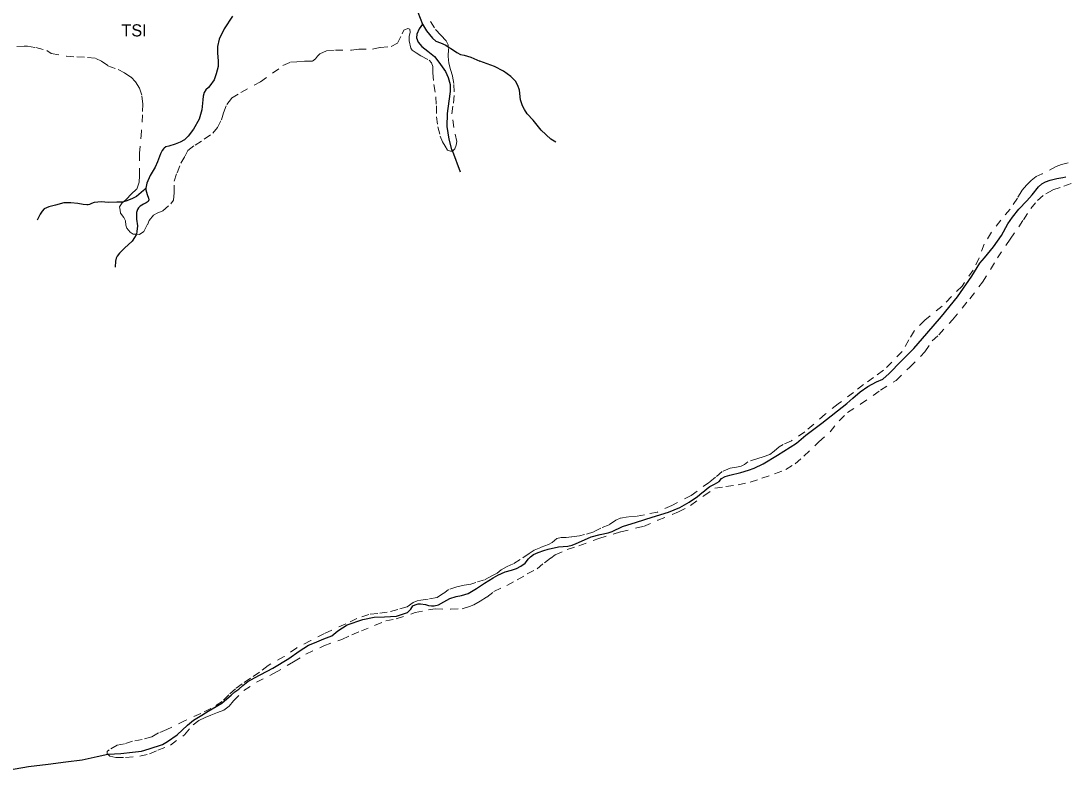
# Model space of a CAD drawing. Extents: x 391.8 to 446, y 8452 to 8507.5.
# Drawn here: x 417.52 to 431.31, y 8489.64 to 8499.54 of the extents above; entities that cross this region are included whole.
import ezdxf
from ezdxf.enums import TextEntityAlignment as Align

# ---------------------------------------------------------------- set-up
doc = ezdxf.new("R2010")
doc.units = 0
doc.header["$LTSCALE"] = 0.064
doc.linetypes.add('LONG_DASHED', pattern=[7.5, 6, -1.5])
doc.linetypes.add('SHORT_DASHED', pattern=[2.7, 1.5, -1.2])
for name, color, linetype, lineweight in [('21', 7, 'SHORT_DASHED', 13), ('7', 7, 'Continuous', 25), ('9', 7, 'LONG_DASHED', 25)]:
    doc.layers.add(name, color=color, linetype=linetype, lineweight=lineweight)
doc.layers.add('61', color=7, linetype='Continuous')

msp = doc.modelspace()

# ---------------------------------------------------------------- linework, layer by layer
at = {"layer": '21'}
for points in [[(423.171, 8499.1938), (423.167, 8499.2216), (423.1413, 8499.273), (423.0706, 8499.35), (422.9866, 8499.444), (422.9094, 8499.5788)], [(422.2702, 8499.1845), (422.418, 8499.1974), (422.5016, 8499.2423), (422.5594, 8499.3643), (422.5851, 8499.4156), (422.6366, 8499.4349), (422.6623, 8499.4285), (422.6687, 8499.39), (422.6559, 8499.3322), (422.6559, 8499.2744), (422.6751, 8499.1781), (422.6944, 8499.1524), (422.7459, 8499.1139), (422.8101, 8499.0754), (422.9194, 8499.0176), (422.9485, 8498.9841), (422.9678, 8498.9328), (422.9678, 8498.8493), (422.9806, 8498.6952), (423.0064, 8498.5347), (423.0128, 8498.4128), (423.0128, 8498.2715), (423.0321, 8498.1367), (423.0642, 8498.0147), (423.0964, 8497.9377), (423.1285, 8497.8799), (423.1606, 8497.8286), (423.1992, 8497.8157), (423.2247, 8497.8157)], [(417.468, 8499.1981), (417.5644, 8499.2045), (417.6094, 8499.2045), (417.7187, 8499.1852), (417.8665, 8499.1467), (417.9244, 8499.1082), (418.1237, 8499.0697), (418.2612, 8499.061), (418.4026, 8499.0546), (418.5119, 8499.0418), (418.5891, 8499.0033), (418.6726, 8498.9455), (418.8076, 8498.8941), (418.8912, 8498.8492), (418.9812, 8498.7914), (419.039, 8498.7336), (419.0905, 8498.6502), (419.1226, 8498.541), (419.1355, 8498.4383), (419.129, 8498.2971), (419.1162, 8498.0788), (419.0905, 8497.7899), (419.0905, 8497.4912), (419.0841, 8497.4077), (419.052, 8497.3114), (418.9812, 8497.2472), (418.917, 8497.183), (418.8762, 8497.1468)], [(419.0479, 8496.7177), (419.0905, 8496.7144), (419.1484, 8496.7529), (419.1934, 8496.8427), (419.2191, 8496.9005), (419.2769, 8496.9711), (419.3219, 8496.9968), (419.3991, 8497.0289), (419.5019, 8497.1188), (419.5405, 8497.1702), (419.5469, 8497.2665), (419.5469, 8497.4205), (419.5855, 8497.5297), (419.6369, 8497.6581), (419.6948, 8497.7544), (419.7269, 8497.825), (419.8234, 8497.8956), (419.9455, 8497.9727), (420.0569, 8498.0518), (420.1212, 8498.1289), (420.1726, 8498.2316), (420.1983, 8498.3215), (420.2433, 8498.4306), (420.3076, 8498.5141), (420.4297, 8498.5911), (420.6869, 8498.7323), (420.8495, 8498.8443), (420.9845, 8498.947), (421.0873, 8498.9919), (421.1709, 8498.9984), (421.2738, 8499.0048), (421.3766, 8499.0048), (421.4152, 8499.0369), (421.4409, 8499.069), (421.473, 8499.1011)], [(421.473, 8499.1011), (421.563, 8499.1396), (421.6787, 8499.1524), (421.8909, 8499.1524), (421.9873, 8499.1653), (422.1673, 8499.1653), (422.2702, 8499.1845)], [(423.2247, 8497.8157), (423.2249, 8497.8157), (423.2571, 8497.8478), (423.2763, 8497.8928), (423.2828, 8497.9441), (423.2441, 8498.1302), (423.2184, 8498.31), (423.2377, 8498.4512), (423.2505, 8498.5989), (423.2441, 8498.708), (423.2248, 8498.8107), (423.1991, 8498.8942), (423.1798, 8498.9776), (423.167, 8499.0675), (423.1734, 8499.1767), (423.171, 8499.1938)], [(431.3642, 8497.6634), (431.2765, 8497.6415), (431.2034, 8497.6123), (431.0207, 8497.5174), (430.9403, 8497.4809), (430.8745, 8497.4298), (430.8161, 8497.3714), (430.7503, 8497.2911), (430.6918, 8497.1962), (430.5968, 8497.0503), (430.4725, 8496.9043), (430.3483, 8496.7437), (430.2526, 8496.587), (430.1868, 8496.4045), (430.1064, 8496.2439), (429.9602, 8496.0322), (429.8214, 8495.8935), (429.697, 8495.7666), (429.4705, 8495.5841), (429.3316, 8495.4454), (429.2585, 8495.3213), (429.1708, 8495.168), (429.0319, 8495.0293), (428.9223, 8494.9199), (428.7907, 8494.825), (428.6592, 8494.7301), (428.5276, 8494.6279), (428.323, 8494.4746), (428.1514, 8494.3395), (427.881, 8494.1059), (427.7056, 8493.9891), (427.596, 8493.938), (427.5448, 8493.9088), (427.479, 8493.8504), (427.4206, 8493.8066), (427.3329, 8493.7774), (427.2598, 8493.7555), (427.1282, 8493.7117), (427.0844, 8493.6752), (427.0405, 8493.6533), (426.982, 8493.6387), (426.8943, 8493.6241), (426.792, 8493.5804), (426.7043, 8493.5074), (426.621, 8493.4409), (426.3798, 8493.2658)], [(418.6718, 8489.8446), (418.6984, 8489.818), (418.7786, 8489.8008), (418.9046, 8489.8008), (419.0937, 8489.818), (419.2197, 8489.8523), (419.3342, 8489.8981), (419.5003, 8489.9667), (419.6836, 8490.104), (419.7982, 8490.2356), (419.8727, 8490.2928), (419.9586, 8490.3328), (420.033, 8490.3614), (420.119, 8490.3958), (420.2049, 8490.4301), (420.2736, 8490.4816), (420.3309, 8490.5502), (420.4684, 8490.6875), (420.6345, 8490.7962), (420.8693, 8490.9163), (421.1271, 8491.0651), (421.2899, 8491.1692), (421.5247, 8491.2779), (421.7653, 8491.3637), (421.897, 8491.424), (422.0216, 8491.4753), (422.1976, 8491.5485), (422.3442, 8491.6071), (422.4835, 8491.6363), (422.7328, 8491.7169), (422.9088, 8491.7535), (422.9968, 8491.7681), (423.202, 8491.7608), (423.356, 8491.7681), (423.4513, 8491.7974), (423.51, 8491.8194), (423.5906, 8491.8707), (423.6786, 8491.9219), (423.7739, 8491.9951), (423.9426, 8492.0757), (424.0819, 8492.1489), (424.2138, 8492.2294), (424.3458, 8492.2953), (424.4411, 8492.3759), (424.5242, 8492.4365), (424.5828, 8492.4804), (424.7434, 8492.5507), (424.8969, 8492.6018), (425.16, 8492.6967), (425.4524, 8492.7842), (425.7521, 8492.8572), (425.9421, 8492.9375), (426.2125, 8493.047), (426.3733, 8493.1346), (426.5487, 8493.2587), (426.6949, 8493.3609), (426.8411, 8493.3828), (427.0019, 8493.4047), (427.1627, 8493.4412), (427.3162, 8493.4923), (427.4843, 8493.5507), (427.6304, 8493.6091), (427.7547, 8493.6821), (427.8716, 8493.7842), (428.069, 8493.974), (428.2186, 8494.1076), (428.3355, 8494.2536), (428.4451, 8494.363), (428.6206, 8494.4725), (428.8837, 8494.655), (429.0883, 8494.7864), (429.271, 8494.9616), (429.4707, 8495.1633), (429.5657, 8495.3093), (429.6534, 8495.3895), (429.8361, 8495.5866), (430.0627, 8495.864), (430.2308, 8496.083), (430.4281, 8496.4041), (430.5962, 8496.6523), (430.7716, 8496.9078), (430.8688, 8497.0558), (430.9565, 8497.1653), (431.0661, 8497.2529), (431.1611, 8497.304), (431.3073, 8497.3551), (431.49, 8497.4208)], [(418.8762, 8497.1468), (418.8591, 8497.1316), (418.827, 8497.0803), (418.8334, 8497.0353), (418.8398, 8496.9968), (418.8848, 8496.939), (418.9041, 8496.8941), (418.9105, 8496.8363), (418.9234, 8496.7978), (418.9684, 8496.7465), (419.007, 8496.7208), (419.0479, 8496.7177)], [(426.3798, 8493.2658), (426.124, 8493.1344), (425.934, 8493.0468), (425.7659, 8493.0103), (425.6562, 8492.9884), (425.5466, 8492.9811), (425.4443, 8492.9665)], [(425.4443, 8492.9665), (425.3858, 8492.9373), (425.2981, 8492.8789), (425.1885, 8492.8351), (425.0935, 8492.784), (424.9692, 8492.7475), (424.9034, 8492.7329), (424.8011, 8492.7183), (424.728, 8492.711), (424.6622, 8492.711), (424.6038, 8492.6964), (424.5453, 8492.6453), (424.4941, 8492.6161), (424.3918, 8492.5796), (424.3041, 8492.5431), (424.2383, 8492.4993), (424.1214, 8492.419), (424.0303, 8492.3641), (423.9499, 8492.3276), (423.8695, 8492.2838), (423.8184, 8492.24), (423.7453, 8492.2035), (423.6503, 8492.1524), (423.5333, 8492.1159), (423.4676, 8492.094), (423.3798, 8492.0794), (423.2848, 8492.0575), (423.1752, 8492.021), (423.124, 8491.9845), (423.0802, 8491.9553), (423.0217, 8491.9188), (422.9048, 8491.8969), (422.8098, 8491.8823), (422.7586, 8491.875), (422.7074, 8491.8531), (422.627, 8491.7947), (422.5028, 8491.7582), (422.3639, 8491.7218), (422.2397, 8491.7072), (422.1227, 8491.6926), (421.9619, 8491.6415), (421.8158, 8491.5685), (421.5348, 8491.4418), (421.3521, 8491.3469), (421.1694, 8491.2521), (421.0012, 8491.1353), (420.7893, 8491.0185), (420.674, 8490.9312), (420.5571, 8490.8509), (420.4478, 8490.778), (420.3581, 8490.7119), (420.2716, 8490.6307), (420.1839, 8490.5431), (420.033, 8490.4515), (419.8997, 8490.3834), (419.6951, 8490.2928), (419.4488, 8490.1727), (419.34, 8490.1269), (419.2514, 8490.0747), (419.1253, 8490.0404), (418.9981, 8490.0188), (418.8914, 8489.9826), (418.7958, 8489.9667), (418.687, 8489.9038), (418.6641, 8489.8809), (418.6641, 8489.8523), (418.6718, 8489.8446)]]:
    msp.add_lwpolyline(points, dxfattribs=at)
at = {"layer": '7'}
for points in [[(422.6813, 8500), (422.6969, 8499.9274), (422.732, 8499.7812), (422.7674, 8499.6536), (422.8294, 8499.4956)], [(420.3187, 8499.6014), (420.2101, 8499.4315), (420.1443, 8499.2953), (420.1189, 8499.1977), (420.1189, 8499.1146), (420.1298, 8499.0061), (420.1298, 8498.9338), (420.1045, 8498.8362), (420.0755, 8498.7603), (420.0212, 8498.6808), (420.0031, 8498.6555), (419.9669, 8498.6266), (419.9452, 8498.5904), (419.9307, 8498.5434), (419.9271, 8498.4928), (419.9132, 8498.3631), (419.8798, 8498.2396), (419.8042, 8498.1085), (419.733, 8498.0152), (419.6841, 8497.9663), (419.6254, 8497.936), (419.5609, 8497.9071), (419.4763, 8497.8827), (419.4363, 8497.8716), (419.414, 8497.856), (419.4051, 8497.8471), (419.3896, 8497.8249), (419.3673, 8497.7805), (419.3295, 8497.6761), (419.2961, 8497.6027), (419.2294, 8497.4939), (419.1865, 8497.3926), (419.1728, 8497.3284)], [(422.8294, 8499.4956), (422.8816, 8499.4051), (422.9606, 8499.3086), (423.0075, 8499.2677), (423.069, 8499.2472), (423.1363, 8499.215), (423.171, 8499.1938)], [(423.171, 8499.1938), (423.2271, 8499.1595), (423.2827, 8499.1185), (423.3325, 8499.0951), (423.3793, 8499.0834), (423.4701, 8499.0571), (423.5862, 8499.0057)], [(424.0047, 8492.2797), (424.0704, 8492.2991), (424.1284, 8492.33), (424.1864, 8492.3724), (424.229, 8492.4265), (424.256, 8492.4536), (424.2986, 8492.4844), (424.3566, 8492.5115), (424.4339, 8492.5385), (424.4919, 8492.5578), (424.6281, 8492.5853), (424.7519, 8492.5969), (424.806, 8492.6085), (424.8601, 8492.6316), (424.9723, 8492.678), (425.0613, 8492.7205), (425.1773, 8492.7475), (425.2817, 8492.7707), (425.3358, 8492.79), (425.4712, 8492.8556), (425.6568, 8492.9136), (425.8657, 8492.9792), (426.0799, 8493.0464), (426.2307, 8493.1082), (426.3545, 8493.1777), (426.4666, 8493.2511), (426.5208, 8493.3013), (426.5556, 8493.3283), (426.5904, 8493.3554), (426.6291, 8493.3824), (426.691, 8493.4133), (426.749, 8493.4519), (426.7838, 8493.4906), (426.8302, 8493.5176), (426.8921, 8493.533), (427.0365, 8493.5692), (427.137, 8493.6001), (427.2144, 8493.6272), (427.3304, 8493.6851), (427.5199, 8493.7971), (427.7713, 8493.9555), (427.8967, 8494.0618), (428.1056, 8494.2202), (428.4382, 8494.4789), (428.5194, 8494.5523), (428.6161, 8494.6334), (428.7166, 8494.7068), (428.8288, 8494.7686), (428.9139, 8494.8034), (428.9963, 8494.8787), (429.1548, 8495.0409), (429.325, 8495.207), (429.4952, 8495.4078), (429.6886, 8495.6319), (429.8988, 8495.8895), (430.0921, 8496.1637), (430.1966, 8496.3337), (430.2584, 8496.4071), (430.3783, 8496.55), (430.4827, 8496.7006), (430.5678, 8496.8551), (430.6266, 8496.9431), (430.7117, 8497.0473), (430.8161, 8497.1593), (430.8896, 8497.2366), (430.9708, 8497.3447), (431.0172, 8497.3834), (431.0636, 8497.4104), (431.1255, 8497.4336), (431.2145, 8497.4529), (431.2918, 8497.4683), (431.3344, 8497.4761)], [(419.1728, 8497.3284), (419.1754, 8497.3037), (419.1932, 8497.2415), (419.2088, 8497.1948), (419.211, 8497.1704), (419.2021, 8497.1526), (419.1799, 8497.1348), (419.1443, 8497.1171), (419.0998, 8497.0904), (419.0775, 8497.0682), (419.062, 8497.046), (419.0508, 8497.006), (419.0485, 8496.9157), (419.0618, 8496.829), (419.0551, 8496.7535), (419.0479, 8496.7177)], [(419.0479, 8496.7177), (419.0462, 8496.7091), (419.024, 8496.6735), (418.9906, 8496.6269), (418.8905, 8496.5358), (418.8238, 8496.4691), (418.7926, 8496.4291), (418.7793, 8496.4002), (418.7704, 8496.3602), (418.7682, 8496.2847)], [(423.4335, 8491.969), (423.5418, 8492.0347), (423.6501, 8492.108), (423.7649, 8492.1755), (423.8267, 8492.2102), (423.9234, 8492.2566), (424.0047, 8492.2797)], [(418.6718, 8489.8446), (418.6751, 8489.8453), (418.8413, 8489.8552), (418.9975, 8489.8718), (419.1172, 8489.8851), (419.2169, 8489.915), (419.3916, 8489.9752), (419.4593, 8490.0157), (419.5886, 8490.1018), (419.725, 8490.2309), (419.8041, 8490.2954), (419.9118, 8490.36), (419.9989, 8490.414), (420.0523, 8490.4473), (420.1797, 8490.5196), (420.2449, 8490.5766), (420.3026, 8490.6266), (420.3501, 8490.671), (420.4019, 8490.7072), (420.4576, 8490.7545), (420.5223, 8490.8047), (420.6085, 8490.8549), (420.8527, 8490.984), (421.0628, 8491.1092), (421.1992, 8491.2096), (421.3213, 8491.2885), (421.4004, 8491.3172), (421.5247, 8491.3689), (421.6324, 8491.412), (421.7114, 8491.4765), (421.8335, 8491.5554), (422.0418, 8491.6272), (422.1926, 8491.6559), (422.3291, 8491.663), (422.4871, 8491.6702), (422.5661, 8491.6989), (422.6308, 8491.7204), (422.6738, 8491.7635), (422.7026, 8491.8065), (422.7335, 8491.8222), (422.7722, 8491.8338), (422.8031, 8491.8338), (422.8689, 8491.8261), (422.9075, 8491.8106), (422.9501, 8491.8068), (422.9849, 8491.8068), (423.0429, 8491.8222), (423.1125, 8491.8608), (423.1899, 8491.9033), (423.275, 8491.9304), (423.3446, 8491.942), (423.4335, 8491.969)], [(417.3473, 8489.6355), (417.6231, 8489.682), (417.8824, 8489.7152), (418.115, 8489.7451), (418.3328, 8489.7722), (418.5322, 8489.8154), (418.6718, 8489.8446)]]:
    msp.add_lwpolyline(points, dxfattribs=at)
at = {"layer": '9'}
for points in [[(422.8294, 8499.4956), (422.7873, 8499.4302), (422.7567, 8499.3639), (422.7515, 8499.3128), (422.772, 8499.2567), (422.8231, 8499.2006), (422.8997, 8499.1393), (422.9866, 8499.0679), (423.0479, 8498.9913), (423.1348, 8498.8688), (423.1713, 8498.7889), (423.1968, 8498.697), (423.1968, 8498.6052), (423.1764, 8498.4776), (423.156, 8498.3143), (423.1508, 8498.1407), (423.1764, 8497.9723), (423.2122, 8497.8396), (423.2247, 8497.8157), (423.3269, 8497.541)], [(424.5923, 8497.9333), (424.5259, 8497.9741), (424.3981, 8498.0915), (424.2908, 8498.2242), (424.2142, 8498.3109), (424.1784, 8498.3671), (424.1529, 8498.413), (424.1273, 8498.4947), (424.112, 8498.6222), (424.0915, 8498.6835), (424.0609, 8498.7396), (423.9983, 8498.8018), (423.8998, 8498.8747), (423.7795, 8498.9329), (423.5862, 8499.0057)], [(419.1728, 8497.3284), (419.1416, 8497.295), (419.0482, 8497.2151), (418.9903, 8497.1839), (418.908, 8497.1551), (418.8762, 8497.1468)], [(418.8762, 8497.1468), (418.8569, 8497.1417), (418.7923, 8497.1417), (418.6833, 8497.1373), (418.6322, 8497.1417), (418.5877, 8497.144), (418.5387, 8497.1417), (418.492, 8497.1351), (418.4564, 8497.124), (418.4297, 8497.1128), (418.4119, 8497.1062), (418.3919, 8497.1062), (418.343, 8497.1128), (418.2759, 8497.1246), (418.1834, 8497.1326), (418.0909, 8497.1326), (417.9783, 8497.1005), (417.8899, 8497.0804), (417.8296, 8497.0523), (417.8014, 8497.0242), (417.7773, 8496.9841), (417.7371, 8496.9037)]]:
    msp.add_lwpolyline(points, dxfattribs=at)

# ---------------------------------------------------------------- texts
at = {"layer": '61'}
msp.add_text('TSI', height=0.16, dxfattribs=at).set_placement((419.0178, 8499.3324), align=Align.CENTER)

doc.saveas('drawing.dxf')
